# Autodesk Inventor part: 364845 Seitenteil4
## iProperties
Company: Hundt & Weber AG Schaltgeräte
Created: 2010-11
Part Number: 364845 Seitenteil4
Material: 1.0120
Document SubType Name: Modeling
Designer: I.Baliuc
Manufacturer: Standard
Standards Organization: Custom
Description: Seitenteil, Trenner
Cost Center: 5,196 kg
Authority: 661896 mm^3
Density: 7.85 g/cm^3
HalbzeugNorm: DIN 174
Zweck: HSLT / HSE - Standardseite
Abmessung: Fl. 120x12-170
SaveDate: 2006-10-28
SaveTime: 20:23
TotalMass: 5,196 kg
TotalVolume: 661896 mm^3
Author: AHausen
Revision Number: 364845
Keywords: 380125
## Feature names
1. Extrusion2
2. Bohrung_Ø13 [Hole]
3. Bohrung2 [Hole]
4. Bohrung3 [Hole]
5. Bohrung_M8_01 [Hole]
6. Bohrung_M8_02 [Hole]
7. Bohrung_M6 [Hole]
8. Bohrung_M5 [Hole]
9. Neue Bohrung (zusätzlich) [Rectangular Pattern]
